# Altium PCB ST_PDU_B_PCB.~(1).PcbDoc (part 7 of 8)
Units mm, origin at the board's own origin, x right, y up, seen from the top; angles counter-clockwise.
Board outline 200 x 200 mm, 6 copper layers (Top Layer, Layer 1, Layer 2, Layer 3, Layer 4, Bottom Layer), stack 3.194 mm thick; 894 components, 723 nets, 3233 pads, 4067 vias.
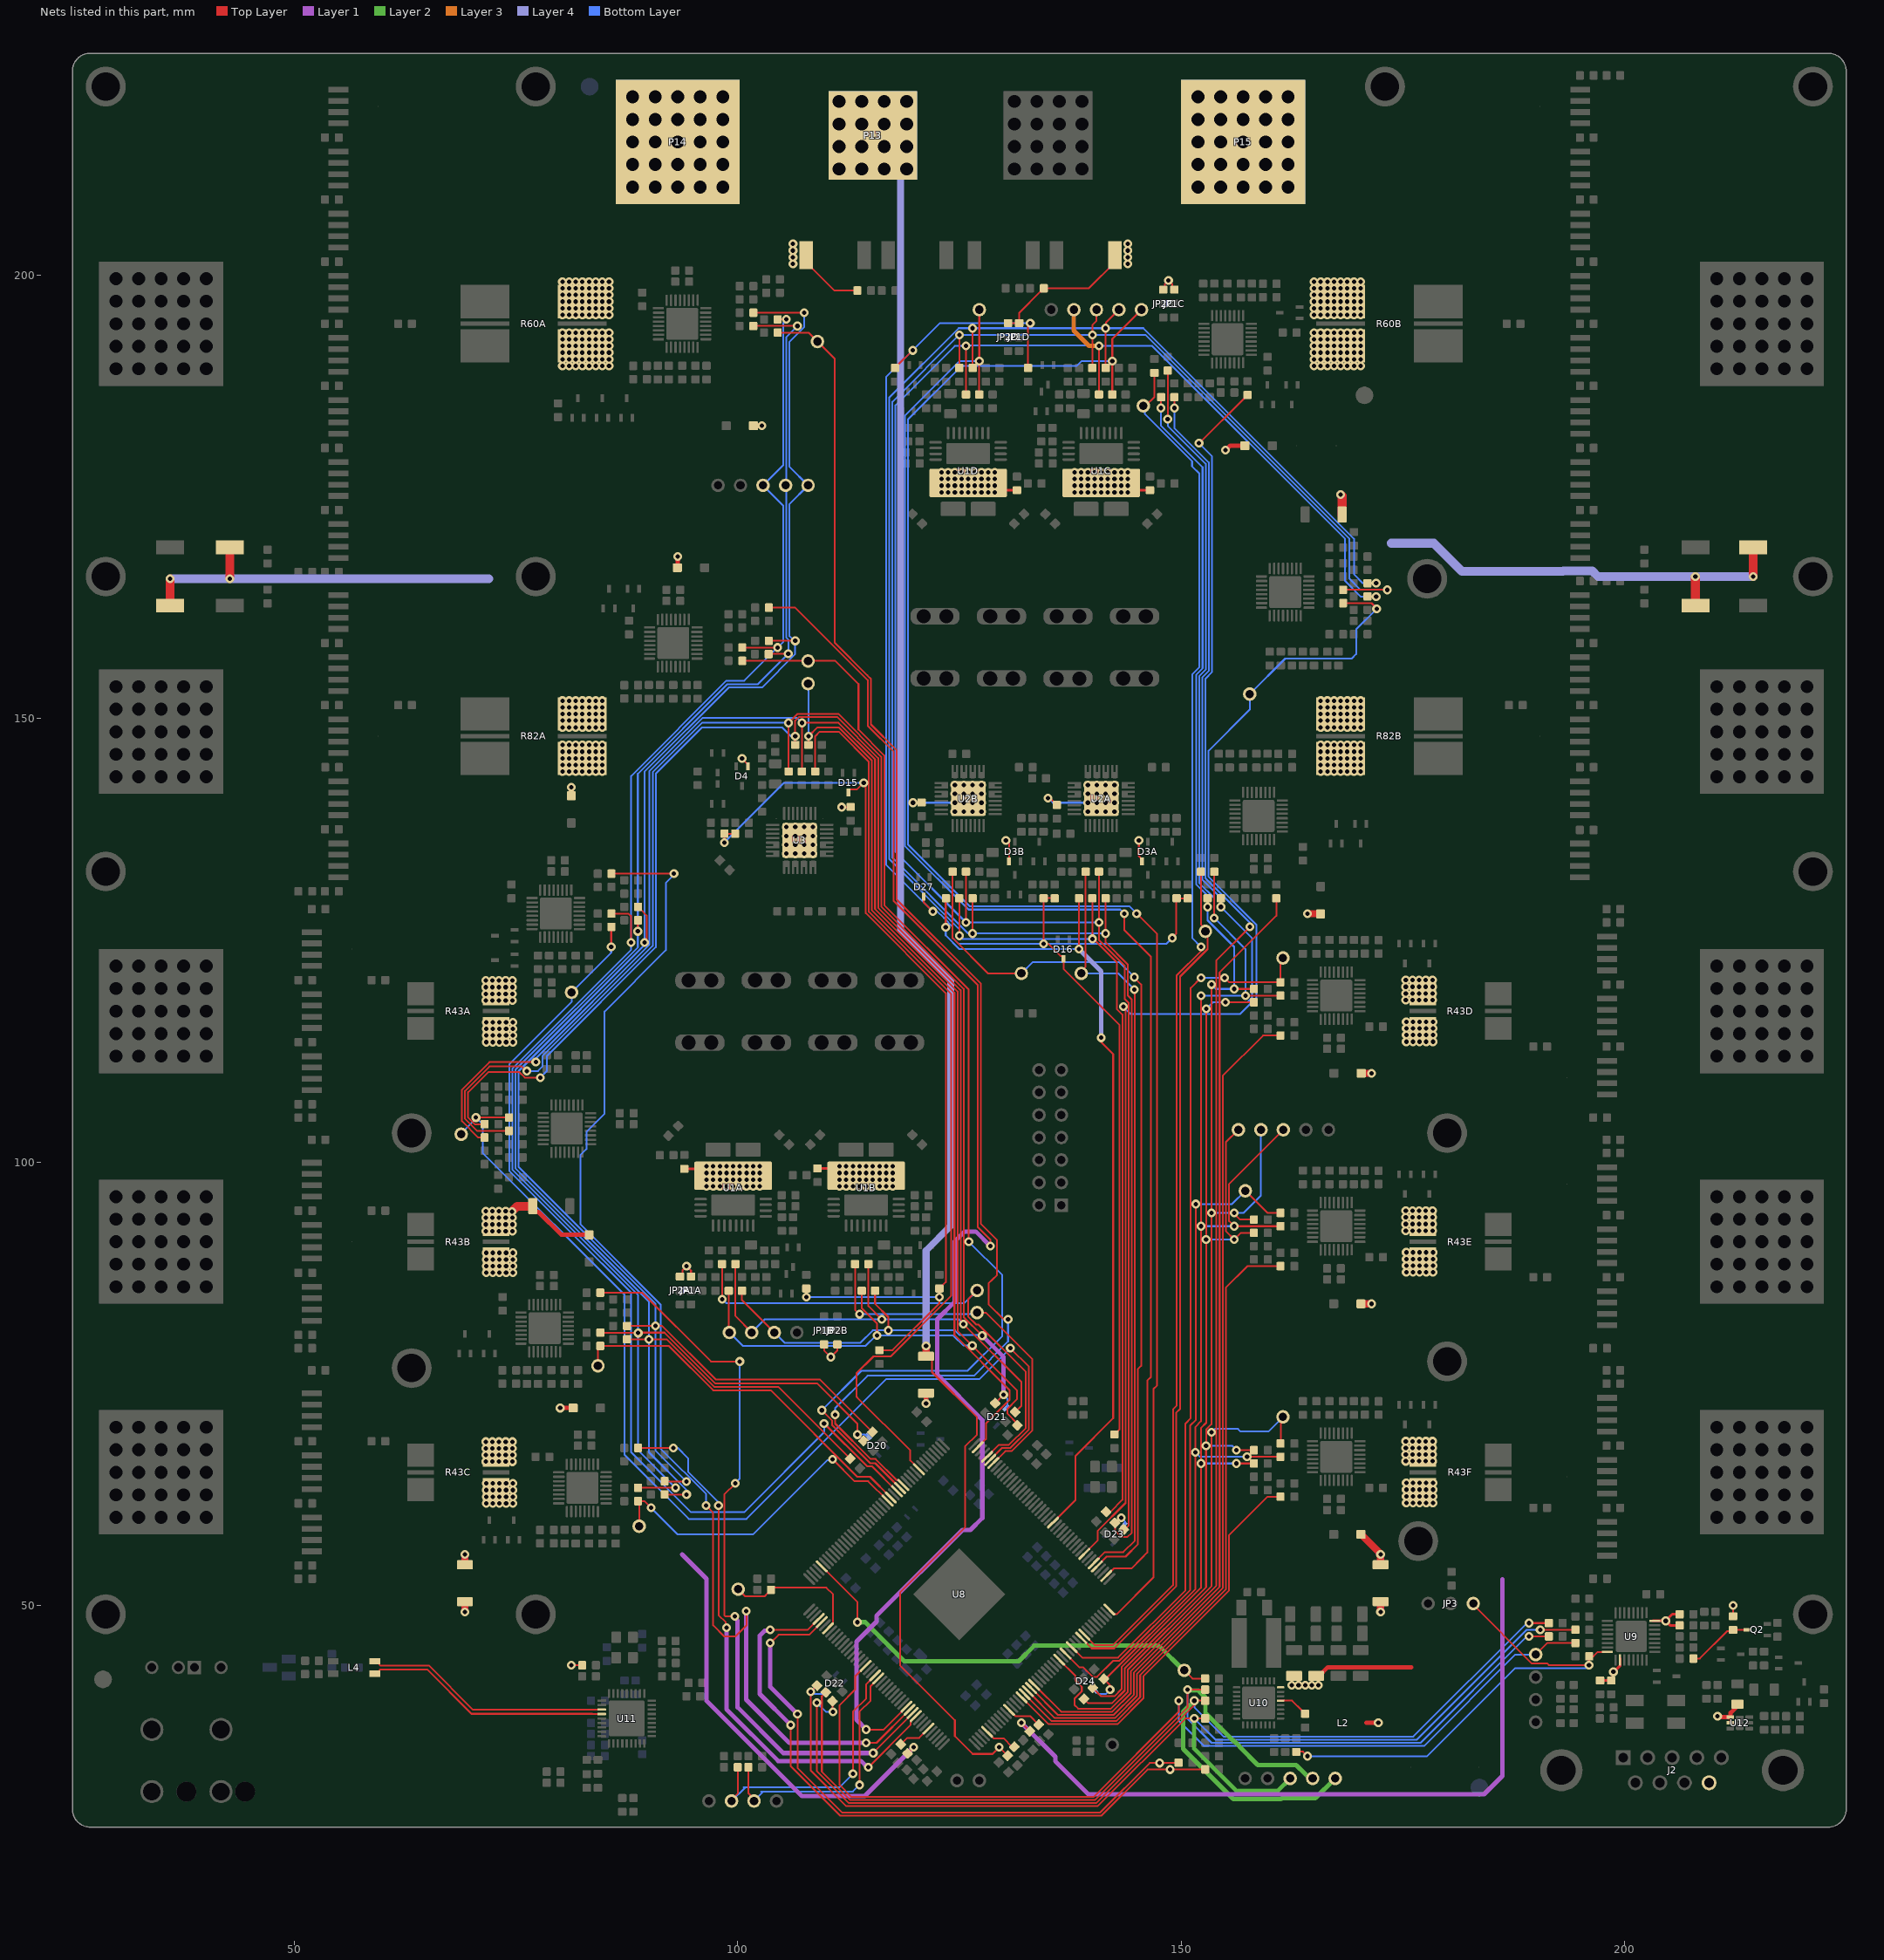
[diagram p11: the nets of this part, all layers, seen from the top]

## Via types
v1: diameter 0.65/1/1/1/1/0.65 (per signal layer), hole 0.5, Top Layer to Bottom Layer, 3739 vias
v2: diameter 0.65/1/1/1/1/0.65 (per signal layer), hole 0.5, Top Layer to Bottom Layer, tented both sides, 296 vias
v3: diameter 0.65, hole 0.5, Top Layer to Bottom Layer, 32 vias

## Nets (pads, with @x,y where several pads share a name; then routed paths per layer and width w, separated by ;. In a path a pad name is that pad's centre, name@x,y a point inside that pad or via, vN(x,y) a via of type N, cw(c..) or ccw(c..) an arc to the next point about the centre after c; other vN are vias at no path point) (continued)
OUTST_A2: R99A.2 U8.32 | length 159.7
  Top Layer w0.2: R99A.2@103.525,162.5 106.5,162.5 114.683,154.317 114.683,149.177 117.6,146.26 117.6,129.41 127.08,119.93 127.08,92.67 128.5,91.25 v1(128.5,90.5) ; v1(114.5,36) 116.468,36 U8.32@119.036,38.568
  Layer 1 w0.5: v1(114.5,36) 113.4,37.1 113.4,45.9 115.679,48.179 115.679,48.828 125.351,58.5 126.25,58.5 127.6,59.85 127.6,70.9 122.5,76 122.5,82.25 124.5,84.25 124.5,91.051 125.599,92.15 126.85,92.15 v1(128.5,90.5)
OUTST_A3: R59A.2 U8.33 | length 140.8
  Top Layer w0.2: R59A.2@85.775,132.5 v1(92.825,132.5) ; v1(96.45,61.25) 97.25,60.45 97.25,47.75 98.5,46.5 99.75,46.5 101.032,47.782 101.032,49.275 v1(100.958,49.348) ; v1(114.5,34.5) 115.675,34.5 U8.33@119.389,38.214
  Layer 1 w0.5: v1(100.958,49.348) 100.958,39.361 105.819,34.5 v1(114.5,34.5)
  Bottom Layer w0.2: v1(92.825,132.5) 92.825,132.383 91.9,131.458 91.9,123.862 85,116.962 85,105.437 82.952,103.388 82.952,101.452 82.295,100.795 82.295,92.95 91.325,83.92 91.325,67.675 96.45,62.55 v1(96.45,61.25)
OUTST_A4: R59B.2 U8.34 | length 84
  Top Layer w0.2: R59B.2@84.525,85.25 89.25,85.25 97,77.5 v1(100.25,77.5) v1@100.5,77.25 ; v1(99.692,48.75) 98.617,48.75 98.5,48.867 98.5,62.5 v1(99.75,63.75) ; v1(115.298,33.35) 115.298,33.39 119.743,37.834 U8.34@119.743,37.861
  Layer 1 w0.5: v1(99.692,48.75) 99.692,48.588 100,48.28 100,38.5 105.15,33.35 v1(115.298,33.35)
  Bottom Layer w0.2: v1(99.75,63.75) 99.75,63.806 100.25,64.306 v1(100.25,77.5)
OUTST_A5: R59C.2 U8.35 | length 63.2
  Top Layer w0.2: R59C.2@88.775,67.75 v1(92.75,67.75) v1@93,67.75 ; v1(97.85,61.25) 97.85,48.905 98.664,48.091 98.664,47.586 v1(98.75,47.5) ; v1(114.75,31.75) 119.5,36.5 119.5,36.884 120.096,37.48 U8.35@120.096,37.507
  Layer 1 w0.5: v1(98.75,47.5) 98.75,38.273 104.573,32.45 113.915,32.45 114.615,31.75 v1(114.75,31.75)
  Bottom Layer w0.2: v1(92.75,67.75) 93.25,67.75 94.425,66.575 94.425,65.07 97.806,61.689 97.806,61.294 v1(97.85,61.25)
OUTST_B1: R80B.2 U8.64 | length 170.2
  Top Layer w0.2: U8.64@133.439,41.043 136.482,38 142.245,38 144.35,40.105 144.35,42.58 154,52.23 154,122.729 v1(157.764,126.493) ; v1(152.032,181.032) 152.057,181.032 157.133,186.108 157.133,186.126 157.482,186.475 R80B.2@157.5,186.475
  Bottom Layer w0.2: v1(152.032,181.032) 153.481,179.582 153.481,155.213 152.75,154.482 152.75,132 157.764,126.986 v1(157.764,126.493)
OUTST_B2: R99B.2 U8.63 | length 110.2
  Top Layer w0.2: U8.63@133.086,40.689 136.125,37.65 142.395,37.65 144.7,39.955 144.7,42.435 154.35,52.085 154.35,121.35 160.75,127.75 R99B.2@160.75,129.725
OUTST_B3: R59D.2 U8.62 | length 96.9
  Top Layer w0.2: U8.62@132.732,40.336 135.768,37.3 142.54,37.3 145.05,39.81 145.05,42.29 154.7,51.94 154.7,109.7 159.25,114.25 R59D.2@161.225,114.25
OUTST_B4: R59E.2 U8.61 | length 72.7
  Top Layer w0.2: U8.61@132.379,39.982 135.411,36.95 142.685,36.95 145.4,39.665 145.4,42.145 155.05,51.795 155.05,85.8 157.5,88.25 R59E.2@161.225,88.25
OUTST_B5: R59F.2 U8.60 | length 46.2
  Top Layer w0.2: U8.60@132.025,39.629 135.054,36.6 142.83,36.6 145.75,39.52 145.75,42 155.4,51.65 155.4,57.9 159.75,62.25 R59F.2@161.225,62.25
PCH_WU: Q2.3 R161.2 R170.2 | length 7.5
  Top Layer w0.2: R161.2@207.775,44 208.5,44 211.592,47.092 212.092,47.092 212.25,47.25 Q2.3@213.892,47.25
PMIC_WKUP: C100.2 JP3.3 R156.1 U9.24 | length 56.9
  Top Layer w0.2: R156.1@163,33.475 163.025,33.5 163.75,33.5 v1(164.25,33) ; JP3.3@182.948,50.202 182.948,50.062 189.573,43.438 191.312,43.438 191.5,43.25 v1(196,43.25) 196,44.225 C100.2@196.025,44.25 196.5,44.25 197,44.75 U9.24@198.273,44.75
  Bottom Layer w0.2: v1(164.25,33) 177.75,33 187.672,42.922 195.658,42.922 195.986,43.25 v1(196,43.25)
PWM_CLK_A: R36.2 U8.141 | length 103.7
  Top Layer w0.2: R36.2@108.75,144.025 108.75,148 109.25,148.5 111.4,148.5 114.8,145.1 114.8,128.195 124.1,118.895 124.1,84.913 117.262,78.075 115.325,78.075 113.4,76.15 113.4,73.527 113.5,73.427 119.464,67.464 119.464,66.332 U8.141@120.45,65.346
PWM_CLK_B: R22A.2 R22B.2 U8.107 | length 94.7
  Top Layer w0.2: v1(123.468,126.468) 123.468,129.693 R22B.2@123.5,129.725 ; U8.107@135.561,59.336 138.1,61.875 138.1,66.85 142.35,71.1 142.35,111.64 142.35,112.15 141,113.5 v1(141,114) ; v1(138.5,124) R22A.2@138.5,129.725
  Layer 4 w0.5: v1(138.5,124) 141,121.5 v1(141,114)
  Bottom Layer w0.2: v1(123.468,126.468) 123.468,125.537 125.005,124 v1(138.5,124)
SPI0_CS0: R11B.2 TP30.1 U8.126 | length 41.5
  Top Layer w0.2: R11B.2@113.25,88.475 113.25,83.325 v1(113.75,82.825) ; TP30.1@127,83 128,83 133.25,77.75 133.25,69.75 130.895,67.395 130.184,67.395 U8.126@128.843,66.053
  Bottom Layer w0.2: v1(113.75,82.825) 126.825,82.825 TP30.1@127,83
SPI0_CS1: R107A.2 TP29.1 U8.127 | length 121.5
  Top Layer w0.2: v1(70.5,105) R107A.2@74.225,105 ; U8.127@128.49,66.407 129.827,67.745 130.75,67.745 132.85,69.845 132.85,76.9 v1(130.75,79)
  Bottom Layer w0.2: TP29.1@68.834,103.124 68.834,103.229 70.5,104.895 v1(70.5,105) 71.25,104.25 71.25,101.01 87.25,85.01 87.25,67 94.5,59.75 101,59.75 116.75,75.5 127.25,75.5 v1(130.75,79)
SPI0_CS2: R38.2 TP25.1 U8.131 | length 101.9
  Top Layer w0.2: R38.2@108,147.025 v1(108,148) 109,149 111.395,149 115.15,145.245 115.15,128.365 124.45,119.065 124.45,80.487 130.667,74.27 130.667,73.167 128,70.5 128,68.746 U8.131@127.075,67.821
  Bottom Layer w0.2: TP25.1@107.575,154.299 108,153.874 v1(108,148)
SPI0_CS6: R11A.2 TP28.1 U8.128 | length 58
  Top Layer w0.2: v1(98.25,84.5) R11A.2@98.25,88.475 ; TP28.1@127,85.5 125.988,84.488 125.988,82.581 126.909,81.659 127.154,81.659 132.5,76.313 132.5,70 130.595,68.095 129.47,68.095 U8.128@128.136,66.76
  Bottom Layer w0.2: v1(98.25,84.5) 98.306,84.5 98.731,84.075 125.575,84.075 TP28.1@127,85.5
SPI0_MISO: D21.3 R14A.2 R14B.2 R41.2 R110A.2 R124.2 TP24.1 | length 210.1
  Top Layer w0.2: R110A.2@74.225,103.5 70.618,103.5 69.263,104.855 69.263,107.995 72.017,110.75 75.658,110.75 76.158,110.25 v1(76.25,110.25) ; R14A.2@100.5,85.475 100.5,84.412 TP24.1@104.14,80.772 ; R41.2@105.75,144.025 v1(105.75,149.5) 106.775,150.525 111.355,150.525 116.2,145.68 116.2,128.8 125.5,119.5 125.5,82.5 v1(127.593,80.407) ; R14B.2@115.5,85.475 115.5,84 117,82.5 v1(117,81) ; R124.2@129.048,72.798 v1(130,73.75)
  Layer 1 w0.5: v1(127.593,80.407) 130,78 130,73.981 v1@130.231,73.75
  Bottom Layer w0.2: v1(76.25,110.25) 77.5,110.25 78,110.75 78,111.942 90.425,124.367 90.425,143.93 95.995,149.5 v1(105.75,149.5) ; TP24.1@104.14,80.772 105.314,79.598 113.848,79.598 115.25,81 v1(117,81) 124.5,81 125.025,80.475 127.525,80.475 v1(127.593,80.407) ; v1@130,73.742 130.448,73.294 130.448,72.448 D21.3@130.284,72.284
SPI0_MOSI: R13A.2 R13B.2 R40.2 R109A.2 R125.2 TP26.1 | length 207.2
  Top Layer w0.2: R109A.2@71.475,104.25 70.363,104.25 69.613,105 69.613,107.85 71.912,110.15 75.35,110.15 76,109.5 v1(77.75,109.5) ; R13A.2@99.75,88.475 99.75,82.622 TP26.1@101.6,80.772 ; R40.2@106.5,147.025 v1(106.5,148) 106.5,149.75 106.925,150.175 111.21,150.175 115.85,145.535 115.85,128.655 125.15,119.355 125.15,82.159 125.468,81.84 v1(125.468,81.718) ; R13B.2@114.75,88.475 114.75,83.75 v1(116.25,82.25) ; v1@125.5,81.687 132,75.187 132,72.5 R125.2@131.298,71.798
  Bottom Layer w0.2: v1(77.75,109.5) 78.5,110.25 78.5,111.947 90.775,124.222 90.775,124.275 90.775,143.77 96.005,149 105,149 106,148 v1(106.5,148) ; TP26.1@101.6,80.772 103.078,82.25 v1(116.25,82.25) 124.937,82.25 v1(125.468,81.718)
SPI0_SCK: R12A.2 R12B.2 R39.2 R108A.2 R126.2 TP27.1 | length 212.4
  Top Layer w0.2: R108A.2@71.475,102.75 70.75,102.75 68.913,104.587 68.913,108.14 72.022,111.25 v1(77.25,111.25) ; TP27.1@99,80.5 R12A.2@99,85.475 ; R39.2@107.25,144.025 v1(107.25,149.5) 111.39,149.5 115.5,145.39 115.5,128.51 124.8,119.21 124.8,80.95 131.5,74.25 131.5,73.23 130.441,72.17 130.441,71.609 131.548,70.502 R126.2@131.548,70.298 ; R12B.2@114,85.475 114,83.5 115.724,81.776 v1(115.724,80.425)
  Bottom Layer w0.2: v1(77.25,111.25) 77.274,111.274 77.274,111.71 90.075,124.512 90.075,144.075 96.075,150.075 106.675,150.075 v1(107.25,149.5) ; TP27.1@98.746,80.5 TP27.1@98.821,80.425 ; TP27.1@99.06,80.772 100.584,79.248 114.425,79.248 115.602,80.425 124.325,80.425 125.468,79.282 v1(126.468,79.282)
SPI2_CS0: R67B.2 TP46.1 U8.80 | length 155.4
  Top Layer w0.2: U8.80@139.096,46.7 140.296,45.5 142.32,45.5 149.1,52.28 149.1,72.1 149.5,72.5 149.5,121 152.25,123.75 v1(152.25,124.25) ; TP46.1@145.75,185.25 146,185.25 147,186.25 R67B.2@147,188.975
  Bottom Layer w0.2: TP46.1@145.75,185.25 145.926,185.074 145.926,184.324 151.25,179 151.25,178.432 152.081,177.601 152.081,155.793 151.253,154.965 151.253,125.247 v1(152.25,124.25)
SPI2_CS1: R87B.2 TP45.1 U8.79 | length 96.5
  Top Layer w0.2: U8.79@138.743,46.346 139.939,45.15 142.465,45.15 149.45,52.135 149.45,71.7 149.9,72.15 149.9,120.9 153,124 153,125.75 TP45.1@152.75,126 152.75,126.279 152.25,126.779 R87B.2@152.25,132.725
SPI2_CS2: R48F.2 TP42.1 U8.72 | length 58
  Top Layer w0.2: U8.72@136.268,43.871 138.095,42.045 138.095,41.534 138.809,40.82 138.809,40.309 138,39.5 138,38.75 138.4,38.35 142.1,38.35 144,40.25 144,42.725 153.425,52.15 v1(153.425,69.5) ; R48F.2@161.225,68.25 161.24,68.265 TP42.1@161.24,70.96
  Bottom Layer w0.2: v1(153.425,69.5) 153.825,69.9 156.419,69.9 156.723,69.596 159.876,69.596 TP42.1@161.24,70.96
SPI2_CS3: R48D.2 TP44.1 U8.76 | length 98.3
  Top Layer w0.2: U8.76@137.682,45.286 138.868,44.1 142.9,44.1 150.5,51.7 150.5,70.5 151.1,71.1 151.1,119.608 v1(152.245,120.753) ; v1(154.925,120.767) 155.442,120.25 R48D.2@161.225,120.25 161.225,122.367 161.5,122.642 TP44.1@161.5,123
  Bottom Layer w0.2: v1(152.245,120.753) 152.252,120.76 154.918,120.76 v1(154.925,120.767)
SPI2_CS4: R48E.2 TP43.1 U8.74 | length 74.2
  Top Layer w0.2: U8.74@136.975,44.578 138.553,43 139,43 139.345,42.655 139.345,42.63 140.034,41.941 140.547,41.941 142.356,43.75 143.045,43.75 151.049,51.754 151.049,70.299 151.675,70.925 v1(151.675,95.25) ; TP43.1@157.244,96.756 159.75,94.25 R48E.2@161.225,94.25
  Bottom Layer w0.2: v1(151.675,95.25) 155.75,95.25 TP43.1@157.25,96.75
SPI2_MISO: D24.3 R50D.1 R50E.1 R50F.1 R69B.1 R89B.1 R141.2 TP49.1 | length 206.7
  Top Layer w0.2: v1(142,40.5) 142,40.993 141.298,41.695 R141.2@141.298,41.702 141.492,41.702 151.624,51.834 151.624,70.124 152.25,70.75 v1(152.25,92.75) v1(152.25,118.75) ; v1(148.5,183.75) R69B.1@148.5,189.225 ; v1(153.75,127.5) R89B.1@153.75,132.725 ; v1(157.277,118.734) 161.209,118.734 R50D.1@161.225,118.75 ; v1(157.446,66.75) R50F.1@161.225,66.75 ; R50E.1@161.225,92.75 v1(156,92.751) 155.425,93.325 155.425,97.513 TP49.1@161.544,103.632
  Bottom Layer w0.2: D24.3@140.284,40.466 140.75,40 141.5,40 v1(142,40.5) ; v1(148.5,183.75) 148.5,183 152.781,178.719 152.781,155.503 152.05,154.772 152.05,131.45 153.75,129.75 v1(153.75,127.5) 157.277,123.973 v1(157.277,118.734) 157.269,118.742 152.258,118.742 v1(152.25,118.75) ; v1(151.624,67.252) 152.126,66.75 v1(157.446,66.75) ; v1(152.25,92.75) v1(156,92.751)
SPI2_MOSI: R49D.2 R49E.2 R49F.2 R68B.2 R88B.2 R139.2 TP47.1 | length 187.2
  Top Layer w0.2: R139.2@139.048,39.452 139.5,39 142.245,39 143.65,40.405 143.65,42.87 152.825,52.045 152.825,68.087 152.85,68.112 152.85,69.85 153.425,70.425 v1(153.425,120) ; v1(147.75,185) R68B.2@147.75,186.225 ; v1(153,128.75) R88B.2@153,129.725 ; v1(156,94.25) 156,94.151 156.651,93.5 R49E.2@158.225,93.5 ; v1(156,119.5) R49D.2@158.225,119.5 ; v1(156.25,67.5) R49F.2@158.225,67.5
  Bottom Layer w0.2: v1(147.75,185) 147.75,183 152.431,178.319 152.431,155.648 151.7,154.917 151.7,131.305 153,130.005 v1(153,128.75) 153,127.25 156,124.25 v1(156,119.5) 153.925,119.5 v1(153.425,120) ; v1(152.825,67.995) 155.755,67.995 v1(156.25,67.5) ; v1(153.425,94.25) v1(156,94.25) 157.039,94.25 159.004,96.215 TP47.1@159.004,103.124
SPI2_SCK: R51D.2 R51E.2 R51F.2 R70B.2 R90B.2 R140.2 TP48.1 | length 191.6
  Top Layer w0.2: R140.2@140.048,40.702 141,39.75 142.5,39.75 143.3,40.55 143.3,43.015 152.25,51.965 152.25,66.117 152.25,70 152.85,70.6 152.85,91.225 v1(152.825,91.25) ; v1(149.25,185) R70B.2@149.25,186.225 ; v1@152.75,91.25 152.837,91.338 152.837,117.237 v1(152.85,117.25) ; v1(154.5,128.75) R90B.2@154.5,129.725 ; v1(155,118) R51D.2@158.225,118 ; v1(156.25,66) R51F.2@158.225,66 ; TP48.1@156.464,103.632 155.05,102.218 155.05,92.2 v1(156,91.25) 156.75,92 R51E.2@158.225,92
  Bottom Layer w0.2: v1(149.25,185) 149.25,182.745 153.131,178.864 153.131,155.358 152.4,154.627 152.4,131.85 154.5,129.75 v1(154.5,128.75) 158,125.25 158,118.5 157.5,118 153.6,118 v1(152.85,117.25) ; v1(152.25,66) v1(156.25,66) ; v1(152.825,91.25) v1(156,91.25)
SPI3_CS0: R159.2 TP36.1 U8.19 | length 111.6
  Top Layer w0.2: U8.19@114.439,43.164 113.25,41.975 113.25,40.5 111.5,38.75 111.5,29.75 112.85,28.4 140.15,28.4 149.75,38 v1(149.75,39.25) ; TP36.1@189.992,44.45 191.292,45.75 R159.2@194.475,45.75
  Bottom Layer w0.2: v1(149.75,39.25) 149.75,37 152.6,34.15 177.4,34.15 187.7,44.45 TP36.1@189.992,44.45
SPI3_CS6: R162.2 TP20.1 U8.172 | length 51.3
  Top Layer w0.2: U8.172@109.49,54.386 109.517,54.386 113.5,50.403 v1(113.5,48.1) ; TP20.1@150.368,42.672 151.29,41.75 R162.2@152.725,41.75
  Layer 2 w0.5: v1(113.5,48.1) 114.4,48.1 118.791,43.709 131.706,43.709 133.446,45.45 147.505,45.45 150.283,42.672 TP20.1@150.368,42.672
SPI3_MISO: D22.3 R131.1 R155.1 R165.1 TP33.1 | length 127.9
  Top Layer w0.2: R131.1@108.952,40.952 v1(108.25,40.25) 108.25,31.364 112.264,27.35 140.6,27.35 150.5,37.25 v1(151.5,37.25) R165.1@152.725,37.25 ; v1(190.5,47.25) R155.1@194.475,47.25
  Layer 2 w0.5: v1(151.5,37.25) 151.456,37.206 151.456,33.879 156.267,29.068 160.89,29.068 TP33.1@162.302,30.48
  Bottom Layer w0.2: v1(108.25,40.25) 108.342,40.25 108.592,40 109.604,40 109.656,40.052 109.802,40.052 D22.3@109.966,40.216 ; v1(151.5,37.25) 153.9,34.85 176.595,34.85 188.995,47.25 v1(190.5,47.25)
SPI3_MOSI: R132.1 R157.1 R163.1 TP34.1 | length 129.4
  Top Layer w0.2: R132.1@109.952,40.202 109.5,39.75 109.5,31.25 112.7,28.05 140.3,28.05 150.75,38.5 v1(150.75,40.5) R163.1@152.725,40.5 ; v1(189.25,46.5) R157.1@191.475,46.5
  Layer 2 w0.5: v1(150.75,40.5) 150.835,40.415 151.962,40.415 152.75,39.626 152.75,37.874 155.899,34.725 155.928,34.725 156.004,34.649 156.052,34.649 156.65,34.051 156.65,34.003 158.653,32 162.987,32 164.107,30.88 164.169,30.88 164.569,30.48 TP34.1@164.846,30.48
  Bottom Layer w0.2: v1(150.75,40.5) 150.75,37.187 153.437,34.5 177,34.5 188.914,46.414 189.164,46.414 v1(189.25,46.5)
SPI3_SCK: R133.1 R154.1 R164.1 TP35.1 | length 135.3
  Top Layer w0.2: v1(108.925,39.023) 108.925,31.314 112.539,27.7 140.45,27.7 151.5,38.75 v1(151.5,39.25) R164.1@152.725,39.25 ; R133.1@110.702,39.202 110.724,39.18 110.724,38.026 v1(110.75,38) ; v1(189.25,48) R154.1@191.475,48
  Layer 2 w0.5: v1(151.5,39.25) 150.25,38 150.25,33.812 155.894,28.168 161.263,28.168 161.345,28.25 165.152,28.25 TP35.1@167.382,30.48
  Bottom Layer w0.2: v1(108.925,39.023) 109.948,38 v1(110.75,38) ; v1(151.5,39.25) 151.5,38.5 154.8,35.2 176.2,35.2 188.914,47.914 189.164,47.914 v1(189.25,48)
SPI5_CS0: R11C.2 TP9.1 U8.88 | length 196.5
  Top Layer w0.2: U8.88@141.925,49.528 142.453,49 142.755,49 146.9,53.145 146.9,74.4 147.3,74.8 147.3,125.7 v1(145,128) ; R11C.2@142.25,186.525 v1(142.25,190.304) 142.25,192.796 TP9.1@145.542,196.088
  Bottom Layer w0.2: v1(142.25,190.304) 138.804,190.304 138.229,189.729 125.229,189.729 119.2,183.7 119.2,135.8 126.2,128.8 144.2,128.8 v1(145,128)
SPI5_CS1: R24A.2 TP52.1 U8.94 | length 86.3
  Top Layer w0.2: TP52.1@138.75,121.25 138.75,121.529 139.25,122.029 R24A.2@139.25,132.725 ; U8.94@140.157,54.74 141.417,56 143.5,56 144.8,57.3 144.8,119.379 v1(144.75,119.429)
  Bottom Layer w0.2: TP52.1@138.75,121.25 142.929,121.25 v1(144.75,119.429)
SPI5_CS3: R107B.2 TP51.1 U8.97 | length 142.3
  Top Layer w0.2: U8.97@139.096,55.8 140.595,57.299 140.595,58.395 143.75,61.55 143.75,117.158 143.5,117.408 v1(143.5,117.5) ; R107B.2@168.275,163 171.488,163 172.057,162.431 v1(172.057,162.351)
  Bottom Layer w0.2: v1(143.5,117.5) 144.325,116.675 156.675,116.675 158.5,118.5 158.5,126.75 153.1,132.15 153.1,146.35 157.75,151 TP51.1@157.75,152.75 161.75,156.75 169.25,156.75 169.75,157.25 169.75,160.044 v1(172.057,162.351)
SPI5_CS5: R24B.2 TP53.1 U8.93 | length 100.9
  Top Layer w0.2: R24B.2@124.25,132.725 124.25,125.25 128.25,121.25 TP53.1@132,121.25 ; U8.93@140.51,54.386 141.624,55.5 143.75,55.5 145.15,56.9 145.15,76.65 145.5,77 145.5,120 144.75,120.75 v1(144.75,120.829)
  Bottom Layer w0.2: TP53.1@132,121.25 133.268,122.518 143.06,122.518 v1(144.75,120.829)
SPI5_CS6: R11D.2 TP4.1 U8.90 | length 176.1
  Top Layer w0.2: R11D.2@127.25,186.525 v1(127.25,190.304) 127.252,190.306 127.252,196.084 127.254,196.086 TP4.1@127.254,196.088 ; U8.90@141.571,53.325 141.598,53.325 142.423,54.15 144.395,54.15 145.5,55.255 146.2,55.955 146.2,75.35 146.6,75.75 146.6,123.15 143.6,126.15 v1(143.6,128)
  Bottom Layer w0.2: v1(127.25,190.304) 125.054,190.304 118.85,184.1 118.85,135.65 126.05,128.45 143.15,128.45 v1(143.6,128)
SPI5_MISO: D23.3 R14C.2 R14D.2 R27A.2 R27B.2 R110B.2 R136.2 TP38.1 | length 250
  Top Layer w0.2: R14D.2@125,189.525 v1(125,193.25) ; v1(126.5,125.75) R27B.2@126.5,129.725 ; R14C.2@140,189.525 v1(140,193.25) 140,194.363 140.462,194.825 TP38.1@140.462,196.088 ; R27A.2@141.5,129.725 v1(141.5,125.75) 141.5,124.762 144,122.262 144,118.75 144.45,118.3 144.45,58.2 143.941,57.691 143.309,57.691 142.57,58.43 142.57,59.276 R136.2@142.548,59.298 142.695,59.298 v1(143.275,59.877) ; R110B.2@168.275,164.5 v1(173.25,164.5)
  Bottom Layer w0.2: v1(141.5,125.75) 126,125.75 117.45,134.3 117.45,185.7 v1(125,193.25) v1(140,193.25) 146,193.25 169,170.25 169,165.75 170.25,164.5 v1(173.25,164.5) ; v1(143.275,59.877) 143.698,59.454 143.698,59.198 D23.3@143.534,59.034
SPI5_MOSI: R13C.2 R13D.2 R26A.2 R26B.2 R109B.2 R137.2 TP39.1 | length 247.5
  Top Layer w0.2: v1(125.75,127) R26B.2@125.75,132.725 ; R13D.2@125.75,186.525 v1(125.75,192) ; R26A.2@140.75,132.725 v1(140.75,127) 140.75,125.017 143.65,122.117 143.65,118.35 144.1,117.9 144.1,59 143.648,58.548 R137.2@143.548,58.548 ; R13C.2@140.75,186.525 v1(140.75,192) ; R109B.2@171.025,163.75 v1(172,163.75)
  Layer 3 w0.5: TP39.1@137.901,196.067 137.901,193.722 139.624,192 v1(140.75,192)
  Bottom Layer w0.2: v1(140.75,127) v1(125.75,127) 117.8,134.95 117.8,185.3 124.5,192 v1(125.75,192) 125.825,192.075 140.675,192.075 v1(140.75,192) 146.75,192 168.5,170.25 168.5,165.5 170.25,163.75 v1(172,163.75)
SPI5_SCK: R12C.2 R12D.2 R25A.2 R25B.2 R108B.2 R135.2 TP37.1 | length 240.2
  Top Layer w0.2: v1(125,125.5) R25B.2@125,129.725 ; R12D.2@126.5,189.525 v1(126.5,194) ; R25A.2@140,129.725 140,125 140.064,125.064 140.208,125.064 142.75,122.522 142.75,117.25 143.4,116.6 143.4,61.9 142.045,60.545 141.551,60.545 R135.2@141.548,60.548 ; R12C.2@141.5,189.525 v1(141.5,194) 141.539,194.039 141.539,194.625 TP37.1@143.002,196.088 ; R108B.2@171.025,165.25 v1(172,165.25)
  Bottom Layer w0.2: v1(140,125.15) 125.35,125.15 v1(125,125.5) 125,126.25 117.1,134.15 117.1,186.163 124.937,194 v1(126.5,194) v1(141.5,194) 145.75,194 169.5,170.25 169.5,166.25 170.5,165.25 v1(172,165.25)
SPI9_CS0: R87A.2 TP18.1 U8.147 | length 131
  Top Layer w0.2: R87A.2@100.525,156.5 111.015,156.5 113.633,153.883 113.633,148.742 116.55,145.825 116.55,128.96 126.03,119.48 126.03,91.045 v1(126.075,91) ; v1(109.5,72) 110.65,70.85 110.65,70.35 114.973,66.027 115.527,66.027 U8.147@118.328,63.225
  Bottom Layer w0.2: v1(109.5,72) 113.95,76.45 114.076,76.45 125.945,76.45 129.85,80.355 129.85,87.225 v1(126.075,91)
SPI9_CS1: R67A.2 TP19.1 U8.146 | length 162.5
  Top Layer w0.2: R67A.2@104.525,193.5 108,193.5 110.95,190.55 110.95,159 110.95,158.55 114.625,154.875 114.625,154.87 115.033,154.462 115.033,149.322 117.95,146.405 117.95,129.555 127.43,120.075 127.43,93 129.25,91.18 129.25,87.25 128.75,86.75 128.3,86.3 128.3,83.95 130,82.25 v1(130.5,82.25) ; v1(111,71.5) 111,70.5 115,66.5 115.548,66.5 117.893,64.155 117.964,64.155 117.991,64.128 118.133,64.128 U8.146@118.682,63.578
  Bottom Layer w0.2: v1(111,71.5) 111,72.25 114.65,75.9 126.65,75.9 130.5,79.75 v1(130.5,82.25)
SPI9_CS2: R48A.2 TP17.1 U8.148 | length 110.4
  Top Layer w0.2: v1(85.75,124.25) 85.75,126.475 R48A.2@85.775,126.5 ; v1(109.75,70.5) 109.775,70.5 114.599,65.677 115.17,65.677 U8.148@117.975,62.871
  Bottom Layer w0.2: v1(85.75,124.25) 85.75,123.596 TP17.1@81.28,119.126 81.28,118.03 74.25,111 74.25,99.01 81.28,91.98 81.28,91.97 88,85.25 88,67.25 94.75,60.5 100.733,60.5 109.75,69.517 v1(109.75,70.5)
SPI9_CS4: R48B.2 TP16.1 U8.150 | length 42.2
  Top Layer w0.2: TP16.1@84.25,77 84.269,77.019 84.269,78.994 R48B.2@84.525,79.25 92.25,79.25 97.25,74.25 103.75,74.25 113.5,64.5 114.932,64.5 U8.150@117.268,62.164
SPI9_CS5: R48C.2 TP15.1 U8.151 | length 38
  Top Layer w0.2: TP15.1@88.9,58.928 88.9,61.625 R48C.2@88.775,61.75 89.5,61.75 v1(90.25,61) ; v1(110.718,66.468) 113.187,64 114.725,64 U8.151@116.914,61.811
  Bottom Layer w0.2: v1(90.25,61) 93.25,58 101.745,58 110.127,66.382 110.632,66.382 v1(110.718,66.468)
SPI9_MISO: D20.3 R50A.1 R50B.1 R50C.1 R69A.1 R89A.1 R120.2 TP13.1 | length 206.7
  Top Layer w0.2: R50B.1@84.525,80.75 84.55,80.725 88.725,80.725 88.75,80.75 91.755,80.75 97.505,75 109,75 113.5,70.5 v1(113.5,69.25) R120.2@114.202,68.548 ; R50A.1@85.775,128 87.688,128 88,127.688 v1(88,124.75) ; R50C.1@88.775,63.25 v1(93,63.25) ; R89A.1@100.525,158 v1(104.5,158) ; R69A.1@104.525,195 v1(105.5,195)
  Bottom Layer w0.2: v1(88.792,80.708) v1@89,80.708 ; v1(93,63.25) 88.792,67.458 88.792,80.5 v1@89,80.708 ; v1(105.5,195) 105.5,194.916 105.15,194.566 105.15,178.556 TP13.1@102.87,176.276 105.15,173.996 105.15,158.952 105.156,158.946 105.156,158.656 v1(104.5,158) 100.75,154.25 98.75,154.25 88,143.5 v1(88,124.75) 88,123.922 74.6,110.522 74.6,99.155 88.792,84.963 88.792,80.916 v1@89,80.708 ; v1(113.5,69.25) 114.354,69.25 114.406,69.198 114.552,69.198 D20.3@114.564,69.186
SPI9_MOSI: R49A.2 R49B.2 R49C.2 R68A.2 R88A.2 R119.2 TP12.1 | length 196.9
  Top Layer w0.2: R49B.2@87.525,80 92.01,80 97.36,74.65 104.6,74.65 R119.2@112.75,66.5 ; v1(88.75,126) 88.75,127.225 R49A.2@88.775,127.25 ; R49C.2@91.775,62.5 v1(94.25,62.5) ; R68A.2@101.775,194.25 v1(106.75,194.25) ; R88A.2@103.5,157.25 103.532,157.282 v1(105.718,157.282)
  Bottom Layer w0.2: v1(94.25,62.5) 94.25,63 90,67.25 v1(90,80) 90,84.25 74.95,99.3 74.95,110.377 88.75,124.177 v1(88.75,126) 88.75,143.75 98.85,153.85 102.287,153.85 105.687,157.25 105.75,157.25 v1(105.718,157.282) 105.718,158.879 105.5,159.097 105.5,193 v1(106.75,194.25)
SPI9_SCK: R51A.2 R51B.2 R51C.2 R70A.2 R90A.2 R121.2 TP14.1 | length 205.8
  Top Layer w0.2: R51B.2@87.525,81.5 91.5,81.5 97.525,75.475 109.275,75.475 R121.2@115.202,69.548 ; R51A.2@88.775,128.75 88.775,128.732 89.124,128.383 89.142,128.383 89.75,127.775 89.75,125.092 89.5,124.842 v1(89.5,124.75) ; R51C.2@91.775,64 91.807,63.968 v1(94.218,63.968) ; R70A.2@101.775,195.75 v1(107.5,195.75) ; R90A.2@103.525,158.75 v1(106.5,158.75)
  Bottom Layer w0.2: v1(94.218,63.968) 90.75,67.437 v1(90.75,81.5) 90.75,84 75.3,99.45 75.3,110.232 89.417,124.349 89.417,124.667 v1(89.5,124.75) 89.5,144 99,153.5 102.75,153.5 106.5,157.25 v1(106.5,158.75) 106.378,158.75 105.85,159.278 105.85,174.176 TP14.1@107.95,176.276 105.85,178.376 105.85,192.464 107.5,194.114 v1(107.5,195.75)
STDBY_NOT_A: D15.3 R5A.2 R5B.2 R33.2 R37.2 R204.2 | length 110.8
  Top Layer w0.2: v1(98.5,136) 98.5,136.975 R33.2@98.525,137 R37.2@99.725,137 ; v1(107.75,84.75) R5A.2@107.75,85.725 ; D15.3@112.5,141.642 112.5,141.874 112.603,141.977 113.452,141.977 v1(114.225,142.75) 114.225,142.633 114.45,142.408 114.45,128.05 123.475,119.025 123.475,86.45 123.117,86.092 123.117,86.074 122.768,85.725 R5B.2@122.75,85.725 v1(122.75,84.75) 122.75,84.058 117.467,78.775 R204.2@116,78.775
  Bottom Layer w0.2: v1(98.5,136) 105.25,142.75 v1(114.225,142.75) ; v1(107.75,84.75) v1(122.75,84.75)
STDBY_NOT_B: D16.3 D27.3 R5C.2 R5D.2 R19A.2 R19B.2 R23A.2 R23B.2 R205.2 | length 192.5
  Top Layer w0.2: R5D.2@117.75,189.525 117.768,189.525 118.117,189.874 118.117,189.892 119.725,191.5 v1(119.75,191.5) ; D27.3@121,129.892 121,129.25 v1(122,128.25) ; R5C.2@132.75,189.525 132.75,194.233 133,194.483 v1(133,194.575) ; R23B.2@135.614,129.75 134.5,129.75 R19B.2@134.5,129.725 v1(134.5,124.575) 135.067,124.575 136.419,123.223 136.647,123.223 136.75,123.12 136.75,121.75 143.05,115.45 143.05,69.825 142.867,69.642 142.867,69.624 142.518,69.275 R205.2@142.5,69.275 ; v1(149,125.25) 149,125.265 149.434,125.7 149.434,129.659 R19A.2@149.5,129.725 R23A.2@150.75,129.725
  Bottom Layer w0.2: v1(133,194.575) 122.825,194.575 116.75,188.5 116.75,133.5 v1(122,128.25) 122.5,128.25 123.25,127.5 124.25,126.5 124.25,125.25 124.925,124.575 v1(134.5,124.575) 148.325,124.575 v1(149,125.25)
TEST0_LED: R142.1 TP41.1 U8.7 | length 15.8
  Top Layer w0.2: TP41.1@100.076,51.816 100.867,51.025 103.05,51.025 103.408,51.383 103.426,51.383 103.775,51.732 R142.1@103.775,51.75 104.025,52 110,52 110.773,51.227 110.773,48.125 110.746,48.098 110.746,47.956 U8.7@110.197,47.407
TRX_N: L4.1 U11.13 | length 27.5
  Top Layer w0.2: L4.1@59.1,42.3 59.341,42.3 59.597,42.556 59.597,42.656 59.714,42.773 64.989,42.773 69.989,37.773 83.594,37.773 83.598,37.769 84.281,37.769 U11.13@84.3,37.75
TRX_P: L4.4 U11.12 | length 27.5
  Top Layer w0.2: L4.4@59.1,43.7 59.341,43.7 59.597,43.444 59.597,43.344 59.714,43.227 65.177,43.227 70.177,38.227 83.594,38.227 83.598,38.231 84.281,38.231 U11.12@84.3,38.25
UART_RX: R196.1 TP2.1 U8.23 | length 30
  Top Layer w0.2: R196.1@101.217,31.75 101.217,28.805 101.854,28.168 TP2.1@101.854,27.94 ; TP2.1@101.902,27.94 TP2.1@101.902,28.072 ; v1(113.75,29.75) 113.75,38 115,39.25 115,40.896 U8.23@115.854,41.75
  Bottom Layer w0.2: TP2.1@101.854,27.94 102.914,29 ; 102.66,29 102.914,29 ; v1(113.75,29.75) 113,29 102.914,29
UART_TX: R195.1 TP1.1 U8.22 | length 31.5
  Top Layer w0.2: TP1.1@99.362,27.94 99.362,28.132 100.017,28.787 R195.1@100.017,31.75 ; v1(113,31) 113,38 114.5,39.5 114.5,41.104 U8.22@115.5,42.104
  Bottom Layer w0.2: TP1.1@99.242,27.82 100.922,29.5 ; 100.668,29.5 111.5,29.5 v1(113,31)
VCC: C88.2 C89.2 C93.2 C94.2 C95.1 C105.2 C108.2 C122.2 D17.C D18.C D19.C J2.9 L2.2 R170.1 R187.2 U9.8 U9.26 U10.32 U12.1 U12.2 | length 31.4
  Top Layer w0.2: v1(81.25,43.25) R187.2@82.475,43.25 R187.2@82.447,43.278 ; U12.2@211.925,36.75 U12.1@211.925,37.4 ; R170.1@212.25,48.775 v1(212.25,50)
  Top Layer w0.3: C108.2@197.25,41.525 C122.2@198.5,41.525 198.683,41.708 198.683,42.433 v1(198.75,42.5) 198.816,42.5 199.5,43.184 U9.26@199.5,43.848 U9.26@199.5,44.023 ; U9.8@203.227,48.25 v1(204.65,48.25) ; C89.2@206.225,47.75 205.15,47.75 v1(204.65,48.25) ; C88.2@206.225,49 205.4,49 v1(204.65,48.25)
  Top Layer w0.5: v1(121.25,72.75) D19.C@121.25,73.919 ; C93.2@165.25,42.05 165.575,42.05 166.55,43.025 175.925,43.025 C95.1@175.95,43 ; 170.903,36.75 171.29,36.75 v1(172.25,36.75) ; v1(210.5,37.5) 210.541,37.5 210.641,37.4 U12.1@211.925,37.4 ; U12.1@211.975,37.45 211.975,37.875 C105.2@212.75,38.65
  Top Layer w0.8: v1(69.25,49.25) D17.C@69.25,50.419 ; v1(172.5,49.25) D18.C@172.5,50.419
  other v1: 162.5,41 163.25,41 164,41 164.75,41 165.5,41
VCC_EXT: D19.A P13.1 R143.2 | length 196.6
  Top Layer w0.2: D19.A@121.25,78.081 121.505,78.081 121.922,77.664 121.922,76.302 127,71.224 127,69.263 125.65,67.913 125.65,58.784 118.35,51.484 118.35,43.194 124.5,37.044 124.5,35.25 126.5,33.25 128.75,33.25 v1(129.5,34) R143.2@130.452,33.048
  Top Layer w0.8: D19.A@121.25,78.081 v1(121.25,79.25)
  Layer 4 w0.8: P13.1@119.075,211.941 119.075,211.658 118.364,210.947 118.364,126.136 124.05,120.45 124.05,92.8 121.25,90 v1(121.25,79.25)
VCC_EXT_MON: R146.2 U8.49 | length 3.5
  Top Layer w0.2: U8.49@128.136,35.74 128.876,35 130,35 R146.2@130.952,34.048
VCCA: C3A.2 C3B.2 C17.2 D4.1 D8A.A D8B.A D8C.A D9A.A D10A.A D14A.A D17.A JP1A.3 JP1B.3 JP2A.3 JP2B.3 P14.1 R43A.2 R43B.2 R43C.2 R60A.2 R82A.2 R144.2 R190.2 Tr_d3.C Tr_d4.C Tr_d18.C U1A.0 U1B.0 U3.0 | length 129.3
  Top Layer w0.2: JP2A.3@93.5,87.075 93.808,87.383 93.808,87.808 v1(94.25,88.25) 94.75,87.75 JP1A.3@94.75,87.075 ; v1(100.5,145.5) 100.5,145.491 101.15,144.841 D4.1@101.15,144.608 ; Tr_d18.C@107.715,202.25 107.715,201.445 110.91,198.25 R190.2@113.5,198.25 ; JP1B.3@109.75,79.425 109.75,78.75 v1(110.5,78) 111.25,78.75 JP2B.3@111.25,79.425 ; v1(111.75,140) 112.725,140 C17.2@112.75,140.025 ; R144.2@119.166,33.314 v1(119.868,34.016)
  Top Layer w0.3: C3A.2@94,99.225 96.225,99.225 v1(96.5,99.5) ; C3B.2@109,99.275 111.275,99.275 v1(111.5,99.5)
  Top Layer w0.5: D14A.A@76.919,95 76.919,94.617 77.188,94.348 77.571,94.348 80.132,91.787 D8B.A@83.25,91.787 ; v1(80,72.25) D8C.A@81.463,72.25 ; D8A.A@81.25,141.287 v1(81.25,142.25) ; D10A.A@93.213,167 93.232,167.018 93.232,168.232 v1(93.25,168.25) ; D9A.A@101.787,183 v1(102.75,183)
  Top Layer w0.8: D17.A@69.25,54.581 v1(69.25,55.75)
  Top Layer w1: Tr_d3.C@36,162.715 v1(36,165.75) ; v1(42.75,165.75) Tr_d4.C@42.75,169.285 ; v2(74.561,94.411) 75.15,95 D14A.A@76.919,95
  Layer 1 w0.5: 93.75,55.75 96.5,53 96.5,39.25 107.25,28.5 114.352,28.5 v1@119.903,34.051
  Layer 4 w1: v1(36,165.75) 36.007,165.743 71.954,165.743
  other v1: 71.65,62.25 72.4,62.25 73.15,62.25 73.9,62.25 71.65,63 72.4,63 73.15,63 73.9,63 71.65,63.75 72.4,63.75 73.15,63.75 73.9,63.75 71.6,66.2 72.35,66.2 73.1,66.2 73.85,66.2 71.6,66.95 72.35,66.95 73.1,66.95 73.85,66.95 71.6,67.7 72.35,67.7 73.1,67.7 73.85,67.7 71.65,88.25 72.4,88.25 73.15,88.25 73.9,88.25 71.65,89 72.4,89 73.15,89 73.9,89 71.65,89.75 72.4,89.75 73.15,89.75 73.9,89.75 71.6,92.2 72.35,92.2 73.1,92.2 73.85,92.2 71.6,92.95 72.35,92.95 73.1,92.95 73.85,92.95 71.6,93.7 72.35,93.7 73.1,93.7 73.85,93.7 96.5,97.25 97.25,97.25 98,97.25 98.75,97.25 99.5,97.25 100.25,97.25 101,97.25 101.75,97.25 102.5,97.25 111.5,97.25 112.25,97.25 113,97.25 113.75,97.25 114.5,97.25 115.25,97.25 116,97.25 116.75,97.25 117.5,97.25 96.5,98 97.25,98 98,98 98.75,98 99.5,98 100.25,98 101,98 101.75,98 102.5,98 111.5,98 112.25,98 113,98 113.75,98 114.5,98 115.25,98 116,98 116.75,98 117.5,98 96.5,98.75 97.25,98.75 98,98.75 98.75,98.75 99.5,98.75 100.25,98.75 101,98.75 101.75,98.75 102.5,98.75 111.5,98.75 112.25,98.75 113,98.75 113.75,98.75 114.5,98.75 115.25,98.75 116,98.75 116.75,98.75 117.5,98.75 97.25,99.5 98,99.5 98.75,99.5 99.5,99.5 100.25,99.5 101,99.5 101.75,99.5 102.5,99.5 112.25,99.5 113,99.5 113.75,99.5 114.5,99.5 115.25,99.5 116,99.5 116.75,99.5 117.5,99.5 71.65,114.25 72.4,114.25 73.15,114.25 73.9,114.25 71.65,115 72.4,115 73.15,115 73.9,115 71.65,115.75 72.4,115.75 73.15,115.75 73.9,115.75 71.6,118.2 72.35,118.2 73.1,118.2 73.85,118.2 71.6,118.95 72.35,118.95 73.1,118.95 73.85,118.95 71.6,119.7 72.35,119.7 73.1,119.7 73.85,119.7 105.5,134.75 106.5,134.75 107.5,134.75 108.5,134.75 105.5,135.75 106.5,135.75 107.5,135.75 108.5,135.75 105.5,136.75 106.5,136.75 107.5,136.75 108.5,136.75 105.5,137.75 106.5,137.75 107.5,137.75 108.5,137.75 80.25,144 81,144 81.75,144 82.5,144 83.25,144 84,144 84.75,144 80.25,144.75 81,144.75 81.75,144.75 82.5,144.75 83.25,144.75 84,144.75 84.75,144.75 80.25,145.5 81,145.5 81.75,145.5 82.5,145.5 83.25,145.5 84,145.5 84.75,145.5 80.25,146.25 81,146.25 81.75,146.25 82.5,146.25 83.25,146.25 84,146.25 84.75,146.25 80.25,147 81,147 81.75,147 82.5,147 83.25,147 84,147 84.75,147 80.25,149 81,149 81.75,149 82.5,149 83.25,149 84,149 84.75,149 80.25,149.75 81,149.75 81.75,149.75 82.5,149.75 83.25,149.75 84,149.75 84.75,149.75 80.25,150.5 81,150.5 81.75,150.5 82.5,150.5 83.25,150.5 84,150.5 84.75,150.5 80.25,151.25 81,151.25 81.75,151.25 82.5,151.25 83.25,151.25 84,151.25 84.75,151.25 80.25,152 81,152 81.75,152 82.5,152 83.25,152 84,152 84.75,152 80.25,190.5 81,190.5 81.75,190.5 82.5,190.5 83.25,190.5 84,190.5 84.75,190.5 80.25,191.25 81,191.25 81.75,191.25 82.5,191.25 83.25,191.25 84,191.25 84.75,191.25 80.25,192 81,192 81.75,192 82.5,192 83.25,192 84,192 84.75,192 80.25,192.75 81,192.75 81.75,192.75 82.5,192.75 83.25,192.75 84,192.75 84.75,192.75 80.25,193.5 81,193.5 81.75,193.5 82.5,193.5 83.25,193.5 84,193.5 84.75,193.5 80.25,195.5 81,195.5 81.75,195.5 82.5,195.5 83.25,195.5 84,195.5 84.75,195.5 80.25,196.25 81,196.25 81.75,196.25 82.5,196.25 83.25,196.25 84,196.25 84.75,196.25 80.25,197 81,197 81.75,197 82.5,197 83.25,197 84,197 84.75,197 80.25,197.75 81,197.75 81.75,197.75 82.5,197.75 83.25,197.75 84,197.75 84.75,197.75 80.25,198.5 81,198.5 81.75,198.5 82.5,198.5 83.25,198.5 84,198.5 84.75,198.5 106.25,201.25 106.25,202 106.25,202.75 106.25,203.5
  other v2: 71.65,61.5 72.4,61.5 73.15,61.5 73.9,61.5 74.65,61.5 74.65,62.25 74.65,63 74.65,63.75 74.6,66.2 74.6,66.95 74.6,67.7 71.6,68.45 72.35,68.45 73.1,68.45 73.85,68.45 74.6,68.45 71.65,87.5 72.4,87.5 73.15,87.5 73.9,87.5 74.65,87.5 74.65,88.25 74.65,89 74.65,89.75 74.6,92.2 74.6,92.95 74.6,93.7 71.6,94.45 72.35,94.45 73.1,94.45 73.85,94.45 71.65,113.5 72.4,113.5 73.15,113.5 73.9,113.5 74.65,113.5 74.65,114.25 74.65,115 74.65,115.75 74.6,118.2 74.6,118.95 74.6,119.7 71.6,120.45 72.35,120.45 73.1,120.45 73.85,120.45 74.6,120.45 80.25,189.75 81,189.75 81.75,189.75 82.5,189.75 83.25,189.75 84,189.75 84.75,189.75 85.5,189.75 85.5,190.5 85.5,191.25 85.5,192 85.5,192.75 85.5,193.5 85.5,195.5 85.5,196.25 85.5,197 85.5,197.75 85.5,198.5 80.25,199.25 81,199.25 81.75,199.25 82.5,199.25 83.25,199.25 84,199.25 84.75,199.25 85.5,199.25
VCCA_MON: R147.2 U8.39 | length 3.8
  Top Layer w0.2: R147.2@118.404,34.33 119.126,35.052 120.469,35.052 U8.39@121.51,36.093
VCCB: C3C.2 C3D.2 C10A.2 C10B.2 D3A.1 D3B.1 D8D.A D8E.A D8F.A D9B.A D10B.A D14B.A D18.A JP1C.3 JP1D.3 JP2C.3 JP2D.3 P15.1 R43D.2 R43E.2 R43F.2 R60B.2 R82B.2 R145.2 R191.2 Tr_d10.C Tr_d13.C Tr_d19.C U1C.0 U1D.0 U2A.0 U2B.0 | length 185.4
  Top Layer w0.2: v1(119.775,140.5) 120.725,140.5 C10B.2@120.75,140.525 ; v1(130.25,136.25) 130.6,135.9 D3B.1@130.6,133.892 ; JP2D.3@130.5,194.575 JP1D.3@131.75,194.575 131.75,195.725 134.158,198.133 134.176,198.133 134.525,198.482 R191.2@134.525,198.5 139.59,198.5 142.535,201.445 Tr_d19.C@142.535,202.25 ; v1@131.784,36.966 R145.2@132.952,35.798 ; v1(135,141) 135.086,140.914 135.311,140.914 135.975,140.25 C10A.2@136,140.25 ; v1(145.25,136.25) 145.25,134.474 145.6,134.124 D3A.1@145.6,133.892 ; JP2C.3@148,198.35 148.182,198.532 148.182,198.982 v1(148.59,199.39) 148.999,198.981 148.999,198.601 JP1C.3@149.25,198.35
  Top Layer w0.3: v1(129,175.5) 129.225,175.725 C3D.2@131.5,175.725 ; v1(144,175.5) 144.225,175.725 C3C.2@146.5,175.725
  Top Layer w0.5: v1(155,180.25) 155.041,180.25 155.541,180.75 D9B.A@157.213,180.75
  Top Layer w0.8: v1(164.25,128) 165.713,128 D10B.A@165.75,127.963 ; D8F.A@170.287,58 170.312,58 172.5,55.812 v1(172.5,55.75) D18.A@172.5,54.581 ; D8E.A@170.287,84 v1(171.5,84) ; D8D.A@170.323,110 v1(171.5,110)
  Top Layer w1: v1(168,175.25) 168.162,175.088 D14B.A@168.162,173 ; Tr_d10.C@208,162.715 v1(208,166) ; v1(214.5,166) Tr_d13.C@214.5,169.285
  Layer 1 w0.5: v1(132,36.75) 135.827,32.923 135.827,32.423 139.559,28.691 184.168,28.691 186.25,30.773 186.25,52.954
  Layer 4 w1: 173.726,169.75 178.5,169.75 181.65,166.6 193.08,166.6 193.13,166.65 196.35,166.65 197,166 v1(208,166) v1(214.5,166)
  Bottom Layer w0.2: v1(119.775,140.5) v1(124.5,140.5) ; v1(135,141) 135.056,141 135.556,140.5 v1(139.5,140.5)
  other v1: 176.15,62.3 176.9,62.3 177.65,62.3 178.4,62.3 176.15,63.05 176.9,63.05 177.65,63.05 178.4,63.05 176.15,63.8 176.9,63.8 177.65,63.8 178.4,63.8 176.1,66.25 176.85,66.25 177.6,66.25 178.35,66.25 176.1,67 176.85,67 177.6,67 178.35,67 176.1,67.75 176.85,67.75 177.6,67.75 178.35,67.75 176.15,88.3 176.9,88.3 177.65,88.3 178.4,88.3 176.15,89.05 176.9,89.05 177.65,89.05 178.4,89.05 176.15,89.8 176.9,89.8 177.65,89.8 178.4,89.8 176.1,92.25 176.85,92.25 177.6,92.25 178.35,92.25 176.1,93 176.85,93 177.6,93 178.35,93 176.1,93.75 176.85,93.75 177.6,93.75 178.35,93.75 176.15,114.3 176.9,114.3 177.65,114.3 178.4,114.3 176.15,115.05 176.9,115.05 177.65,115.05 178.4,115.05 176.15,115.8 176.9,115.8 177.65,115.8 178.4,115.8 176.1,118.25 176.85,118.25 177.6,118.25 178.35,118.25 176.1,119 176.85,119 177.6,119 178.35,119 176.1,119.75 176.85,119.75 177.6,119.75 178.35,119.75 124.5,139.5 125.5,139.5 126.5,139.5 127.5,139.5 139.5,139.5 140.5,139.5 141.5,139.5 142.5,139.5 125.5,140.5 126.5,140.5 127.5,140.5 140.5,140.5 141.5,140.5 142.5,140.5 124.5,141.5 125.5,141.5 126.5,141.5 127.5,141.5 139.5,141.5 140.5,141.5 141.5,141.5 142.5,141.5 124.5,142.5 125.5,142.5 126.5,142.5 127.5,142.5 139.5,142.5 140.5,142.5 141.5,142.5 142.5,142.5 165.75,144 166.5,144 167.25,144 168,144 168.75,144 169.5,144 170.25,144 165.75,144.75 166.5,144.75 167.25,144.75 168,144.75 168.75,144.75 169.5,144.75 170.25,144.75 165.75,145.5 166.5,145.5 167.25,145.5 168,145.5 168.75,145.5 169.5,145.5 170.25,145.5 165.75,146.25 166.5,146.25 167.25,146.25 168,146.25 168.75,146.25 169.5,146.25 170.25,146.25 165.75,147 166.5,147 167.25,147 168,147 168.75,147 169.5,147 170.25,147 165.75,149 166.5,149 167.25,149 168,149 168.75,149 169.5,149 170.25,149 165.75,149.75 166.5,149.75 167.25,149.75 168,149.75 168.75,149.75 169.5,149.75 170.25,149.75 165.75,150.5 166.5,150.5 167.25,150.5 168,150.5 168.75,150.5 169.5,150.5 170.25,150.5 165.75,151.25 166.5,151.25 167.25,151.25 168,151.25 168.75,151.25 169.5,151.25 170.25,151.25 165.75,152 166.5,152 167.25,152 168,152 168.75,152 169.5,152 170.25,152 123,175.5 123.75,175.5 124.5,175.5 125.25,175.5 126,175.5 126.75,175.5 127.5,175.5 128.25,175.5 138,175.5 138.75,175.5 139.5,175.5 140.25,175.5 141,175.5 141.75,175.5 142.5,175.5 143.25,175.5 123,176.25 123.75,176.25 124.5,176.25 125.25,176.25 126,176.25 126.75,176.25 127.5,176.25 128.25,176.25 129,176.25 138,176.25 138.75,176.25 139.5,176.25 140.25,176.25 141,176.25 141.75,176.25 142.5,176.25 143.25,176.25 144,176.25 123,177 123.75,177 124.5,177 125.25,177 126,177 126.75,177 127.5,177 128.25,177 129,177 138,177 138.75,177 139.5,177 140.25,177 141,177 141.75,177 142.5,177 143.25,177 144,177 123,177.75 123.75,177.75 124.5,177.75 125.25,177.75 126,177.75 126.75,177.75 127.5,177.75 128.25,177.75 129,177.75 138,177.75 138.75,177.75 139.5,177.75 140.25,177.75 141,177.75 141.75,177.75 142.5,177.75 143.25,177.75 144,177.75 165.75,190.5 166.5,190.5 167.25,190.5 168,190.5 168.75,190.5 169.5,190.5 170.25,190.5 165.75,191.25 166.5,191.25 167.25,191.25 168,191.25 168.75,191.25 169.5,191.25 170.25,191.25 165.75,192 166.5,192 167.25,192 168,192 168.75,192 169.5,192 170.25,192 165.75,192.75 166.5,192.75 167.25,192.75 168,192.75 168.75,192.75 169.5,192.75 170.25,192.75 165.75,193.5 166.5,193.5 167.25,193.5 168,193.5 168.75,193.5 169.5,193.5 170.25,193.5 165.75,195.5 166.5,195.5 167.25,195.5 168,195.5 168.75,195.5 169.5,195.5 170.25,195.5 165.75,196.25 166.5,196.25 167.25,196.25 168,196.25 168.75,196.25 169.5,196.25 170.25,196.25 165.75,197 166.5,197 167.25,197 168,197 168.75,197 169.5,197 170.25,197 165.75,197.75 166.5,197.75 167.25,197.75 168,197.75 168.75,197.75 169.5,197.75 170.25,197.75 165.75,198.5 166.5,198.5 167.25,198.5 168,198.5 168.75,198.5 169.5,198.5 170.25,198.5 144,201.25 144,202 144,202.75 144,203.5
  other v2: 175.4,61.55 176.15,61.55 176.9,61.55 177.65,61.55 178.4,61.55 175.4,62.3 175.4,63.05 175.4,63.8 175.35,66.25 175.35,67 175.35,67.75 175.35,68.5 176.1,68.5 176.85,68.5 177.6,68.5 178.35,68.5 175.4,87.55 176.15,87.55 176.9,87.55 177.65,87.55 178.4,87.55 175.4,88.3 175.4,89.05 175.4,89.8 175.35,92.25 175.35,93 175.35,93.75 175.35,94.5 176.1,94.5 176.85,94.5 177.6,94.5 178.35,94.5 175.4,113.55 176.15,113.55 176.9,113.55 177.65,113.55 178.4,113.55 175.4,114.3 175.4,115.05 175.4,115.8 175.35,118.25 175.35,119 175.35,119.75 175.35,120.5 176.1,120.5 176.85,120.5 177.6,120.5 178.35,120.5 165,189.75 165.75,189.75 166.5,189.75 167.25,189.75 168,189.75 168.75,189.75 169.5,189.75 170.25,189.75 165,190.5 165,191.25 165,192 165,192.75 165,193.5 165,195.5 165,196.25 165,197 165,197.75 165,198.5 165,199.25 165.75,199.25 166.5,199.25 167.25,199.25 168,199.25 168.75,199.25 169.5,199.25 170.25,199.25
VCCB_MON: R148.2 U8.56 | length 4
  Top Layer w0.2: U8.56@130.611,38.214 131.325,37.5 133,37.5 R148.2@133.952,36.548
VREF: C99.2 U10.29 | length 3.4
  Top Layer w0.2: U10.29@161.227,39.25 162.525,39.25 163.633,38.142 163.633,38.124 163.982,37.775 C99.2@164,37.775
WDI: R65.2 U8.4 | length 74.8
  Top Layer w0.2: v1(103.675,47.25) 107.919,47.25 U8.4@109.136,48.468 ; v1(106,36.5) 106,31.844 111.544,26.3 141.045,26.3 146.23,31.485 v1(148.774,31.485) 152.71,31.485 R65.2@152.725,31.5
  Layer 1 w0.5: v1(103.675,47.25) 103.56,47.135 103.049,47.135 102.5,46.587 102.5,40 v1(106,36.5)
WK_LPM: R52.2 U8.5 | length 69.5
  Top Layer w0.2: v1(103.675,45.75) 104.619,46.694 108.069,46.694 U8.5@109.49,48.114 ; v1(106.75,37.75) 106.75,31.68 111.78,26.65 140.9,26.65 146.473,32.223 v1(147.585,32.223) ; v1@147.612,32.25 R52.2@149.725,32.25
  Layer 1 w0.5: v1(103.675,45.75) 103.675,40.825 v1(106.75,37.75)
pads on no net: D1A.2 D1B.2 D1C.2 D1D.2 D2A.2 D2B.2 D5.2 D6A.2 D6B.2 D6C.2 D6D.2 D6E.2 D6F.2 D7A.2 D7B.2 D11A.2 D11B.2 D12.2 D13.2 D20.2 D21.2 D22.2 D23.2 D24.2 D28A.2 D28B.2 Designator65.1 Designator66.1 Designator66_1.1 Designator72.0 Designator73.0 Designator75.0 Designator76.0 J1.7 J1.8 J1.13 J2.1 J2.6 J2.8 J3. U1A.7 U1A.8 U1A.19 U1B.7 U1B.8 U1B.19 U1C.7 U1C.8 U1C.19 U1D.7 U1D.8 U1D.19 U2A.5 U2A.6 U2A.7 U2A.8 U2A.20 U2A.25 U2A.26 U2A.27 U2A.28 U2A.29 U2A.30 U2A.31 U2A.32 U2A.TAB U2B.5 U2B.6 U2B.7 U2B.8 U2B.20 U2B.25 U2B.26 U2B.27 U2B.28 U2B.29 U2B.30 U2B.31 U2B.32 U2B.TAB U3.1 U3.2 U3.5 U3.6 U3.7 U3.8 U3.20 U3.23 U3.24 U3.25 U3.26 U3.31 U3.32 U3.TAB U4A.11 U4A.14 U4A.16 U4A.17 U4A.22 U4A.26 U4A.32 U4B.11 U4B.14 U4B.16 U4B.17 U4B.22 U4B.26 U4B.32 U4C.11 U4C.14 U4C.16 U4C.17 U4C.22 U4C.26 U4C.32 U4D.11 U4D.14 U4D.16 U4D.17 U4D.22 U4D.26 U4D.32 U4E.11 U4E.14 U4E.16 U4E.17 U4E.22 U4E.26 U4E.32 U4F.11 U4F.14 U4F.16 U4F.17 U4F.22 U4F.26 U4F.32 U5A.11 U5A.14 U5A.16 U5A.17 U5A.22 U5A.26 U5A.32 U5B.11 U5B.14 U5B.16 U5B.17 U5B.22 U5B.26 U5B.32 U6A.11 U6A.14 U6A.16 U6A.17 U6A.22 U6A.26 U6A.32 U6B.11 U6B.14 U6B.16 U6B.17 U6B.22 U6B.26 U6B.32 U8.10 U8.28 U8.29 U8.30 U8.36 U8.37 U8.38 U8.40 U8.41 U8.42 U8.43 U8.45 U8.46 U8.47 U8.48 U8.50 U8.55 U8.57 U8.58 U8.59 U8.65 U8.66 U8.67 U8.122 U9.4 U9.5 U9.6 U9.7 U9.9 U9.13 U9.14 U9.18 U9.25 U9.27 U9.32 U10.1 U10.4 U10.6 U10.7 U10.8 U10.9 U10.16 U10.17 U10.19 U10.24 U10.25 U10.28 U10.30 U11.20 U11.28 U11.30 U11.31 U11.34 X1.2 X1.4 X2.2 X2.4 ZD1A.2 ZD1B.2 ZD1C.2 ZD1D.2 ZD1E.2 ZD1F.2 ZD2A.2 ZD2B.2 ZD3A.2 ZD3B.2
copper on no net:
  other v1: 98,94.5 99.5,94.5 101,94.5 113,94.5 114.5,94.5 116,94.5 98,95.75 99.5,95.75 101,95.75 113,95.75 114.5,95.75 116,95.75 124.5,179.25 126,179.25 127.5,179.25 139.5,179.25 139.5,179.25 141,179.25 141,179.25 142.5,179.25 142.5,179.25 124.5,180.5 126,180.5 127.5,180.5 139.5,180.5 139.5,180.5 141,180.5 141,180.5 142.5,180.5 142.5,180.5

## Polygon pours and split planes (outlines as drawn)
GND on Layer 1 "GND_L02_P606" (solid, pour order 606): 115,75.25 115,225 135,225 135,75.25
VCCB on Layer 1 "VCCB_L02_P604" (solid, remove dead copper, pour order 604): 135,156 135,140 135,76.5 159,52.5 225,52.5 225,223 ccw(c223,223) 223,225 135,225
VCCA on Layer 1 "VCCA_L02_P591" (solid, pour order 591): 115,140.25 115,130.75 115,76.5 91,52.5 25,52.5 25,223 cw(c27,223) 27,225 115,225
GND on Layer 1 "GND_L02_P278" (solid, remove dead copper, pour order 278): 91.5,52 116,76.5 134,76.5 158.5,52 225,52 225,27 cw(c223,27) 223,25 27,25 cw(c27,27) 25,27 25,52
GND on Layer 1 "GND_L02_P002" (solid, pour order 2): 157,137.25 157,140.75 160.5,140.75 160.5,137.25
GND on Layer 1 "GND_L02_P590" (solid, pour order 590): 130,220.75 130,210.75 140,210.75 140,220.75
VCC_EXT on Layer 1 "VCC_EXT_L02_P547" (solid, pour order 547): 120.25,220.75 120.25,210.75 110.25,210.75 110.25,220.75
OUT_A6 on Layer 1 "OUT_A6_L02_P282" (solid, pour order 282): 99.25,100.5 99.25,114.5 92.5,114.5 92.5,103.75 95.75,100.5
OUT_A9 on Layer 1 "OUT_A9_L02_P546" (solid, pour order 546): 114.75,100.5 114.75,114.5 121.5,114.5 121.5,103.75 118.25,100.5
OUT_A8 on Layer 1 "OUT_A8_L02_P521" (solid, pour order 521): 114.25,100.5 114.25,114.5 107.5,114.5 107.5,103.75 110.75,100.5
OUT_A7 on Layer 1 "OUT_A7_L02_P283" (solid, pour order 283): 99.75,100.5 99.75,114.5 106.5,114.5 106.5,103.75 103.25,100.5
VCCA on Layer 1 "VCCA_L02_P508" (solid, pour order 508): 103,100 103,96.75 96,96.75 96,100
VCCA on Layer 1 "VCCA_L02_P495" (solid, pour order 495): 118,100 118,96.75 111,96.75 111,100
VCCB on Layer 1 "VCCB_L02_P476" (solid, pour order 476): 137.5,175 137.5,178.25 144.5,178.25 144.5,175
VCCB on Layer 1 "VCCB_L02_P459" (solid, pour order 459): 122.5,175 122.5,178.25 129.5,178.25 129.5,175
VCCB on Layer 1 "VCCB_L02_P454" (solid, pour order 454): 139,139 139,143 143,143 143,139
VCCB on Layer 1 "VCCB_L02_P449" (solid, pour order 449): 124,139 124,143 128,143 128,139
VCCA on Layer 1 "VCCA_L02_P443" (solid, pour order 443): 105,134.25 105,138.25 109,138.25 109,134.25
GND on Layer 1 "GND_L02_P438" (solid, pour order 438): 157,37.25 157,40.75 160.5,40.75 160.5,37.25
GND on Layer 1 "GND_L02_P433" (solid, pour order 433): 85.75,35.5 85.75,39 89.25,39 89.25,35.5
GND on Layer 1 "GND_L02_P428" (solid, pour order 428): 80.75,61.5 80.75,65 84.25,65 84.25,61.5
GND on Layer 1 "GND_L02_P423" (solid, pour order 423): 76.5,79.5 76.5,83 80,83 80,79.5
GND on Layer 1 "GND_L02_P418" (solid, pour order 418): 79,102 79,105.5 82.5,105.5 82.5,102
GND on Layer 1 "GND_L02_P413" (solid, pour order 413): 77.75,126.25 77.75,129.75 81.25,129.75 81.25,126.25
GND on Layer 1 "GND_L02_P408" (solid, pour order 408): 91,156.75 91,160.25 94.5,160.25 94.5,156.75
GND on Layer 1 "GND_L02_P403" (solid, pour order 403): 92,192.75 92,196.25 95.5,196.25 95.5,192.75
GND on Layer 1 "GND_L02_P398" (solid, pour order 398): 153.5,191 153.5,194.5 157,194.5 157,191
GND on Layer 1 "GND_L02_P393" (solid, pour order 393): 160,162.5 160,166 163.5,166 163.5,162.5
GND on Layer 1 "GND_L02_P388" (solid, pour order 388): 165.75,117 165.75,120.5 169.25,120.5 169.25,117
GND on Layer 1 "GND_L02_P383" (solid, pour order 383): 199,44.75 199,48.25 202.5,48.25 202.5,44.75
GND on Layer 1 "GND_L02_P378" (solid, pour order 378): 165.75,65 165.75,68.5 169.25,68.5 169.25,65
GND on Layer 1 "GND_L02_P374" (solid, pour order 374): 165.75,91 165.75,94.5 169.25,94.5 169.25,91
OUT_B2 on Layer 1 "OUT_B2_L02_P266" (solid, pour order 266): 194,130.5 225,130.5 225,165.5 194,165.5
OUT_B1 on Layer 1 "OUT_B1_L02_P023" (solid, pour order 23): 194,222.5 225,222.5 225,166.5 194,166.5
OUT_B9 on Layer 1 "OUT_B9_L02_P297" (solid, pour order 297): 125.75,174.5 125.75,160.5 119,160.5 119,171.25 122.25,174.5
OUT_B6 on Layer 1 "OUT_B6_L02_P285" (solid, pour order 285): 141.25,174.5 141.25,160.5 148,160.5 148,171.25 144.75,174.5
OUT_B7 on Layer 1 "OUT_B7_L02_P286" (solid, pour order 286): 140.75,174.5 140.75,160.5 134,160.5 134,171.25 137.25,174.5
OUT_B8 on Layer 1 "OUT_B8_L02_P296" (solid, pour order 296): 126.25,174.5 126.25,160.5 133,160.5 133,171.25 129.75,174.5
OUT_B11 on Layer 1 "OUT_B11_L02_P364" (solid, pour order 364): 140,155.5 140,146.25 138.75,145 138.75,141 136.5,141 134.5,143 134.5,155.5
OUT_B10 on Layer 1 "OUT_B10_L02_P363" (solid, pour order 363): 142,155.5 142,146.25 143.25,145 143.25,141 145.5,141 147.5,143 147.5,155.5
OUT_B13 on Layer 1 "OUT_B13_L02_P355" (solid, pour order 355): 125,155.5 125,146.25 123.75,145 123.75,141 121.5,141 119.5,143 119.5,155.5
OUT_B12 on Layer 1 "OUT_B12_L02_P362" (solid, pour order 362): 127,155.5 127,146.25 128.25,145 128.25,141 130.5,141 132.5,143 132.5,155.5
NetR82B_1 on Layer 1 "NETR82B_1_L02_P032" (solid, pour order 32): 193,130.5 180.5,130.5 173,138 173,157 181.5,165.5 193,165.5
NetR43A_1 on Layer 1 "NETR43A_1_L02_P272" (solid, pour order 272): 54,127.5 65.5,127.5 68.5,124.5 68.5,109.5 65.5,106.5 54,106.5
OUT_B4 on Layer 1 "OUT_B4_L02_P332" (solid, pour order 332): 198.75,78 225,78 225,103 198.75,103 196.75,101 196.75,80
NetR43B_1 on Layer 1 "NETR43B_1_L02_P284" (solid, pour order 284): 54.175,101.575 65.675,101.575 68.675,98.575 68.675,83.575 65.675,80.575 54.175,80.575
OUT_A4 on Layer 1 "OUT_A4_L02_P281" (solid, pour order 281): 51.25,78.5 25,78.5 25,103.5 51.25,103.5 53.25,101.5 53.25,80.5
NetR43C_1 on Layer 1 "NETR43C_1_L02_P309" (solid, pour order 309): 54,75.5 65.5,75.5 68.5,72.5 68.5,57.5 65.5,54.5 54,54.5
NetR43F_1 on Layer 1 "NETR43F_1_L02_P345" (solid, pour order 345): 196,75 184.5,75 181.5,72 181.5,57 184.5,54 196,54
OUT_B5 on Layer 1 "OUT_B5_L02_P344" (solid, pour order 344): 198.75,52 225,52 225,77 198.75,77 196.75,75 196.75,54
